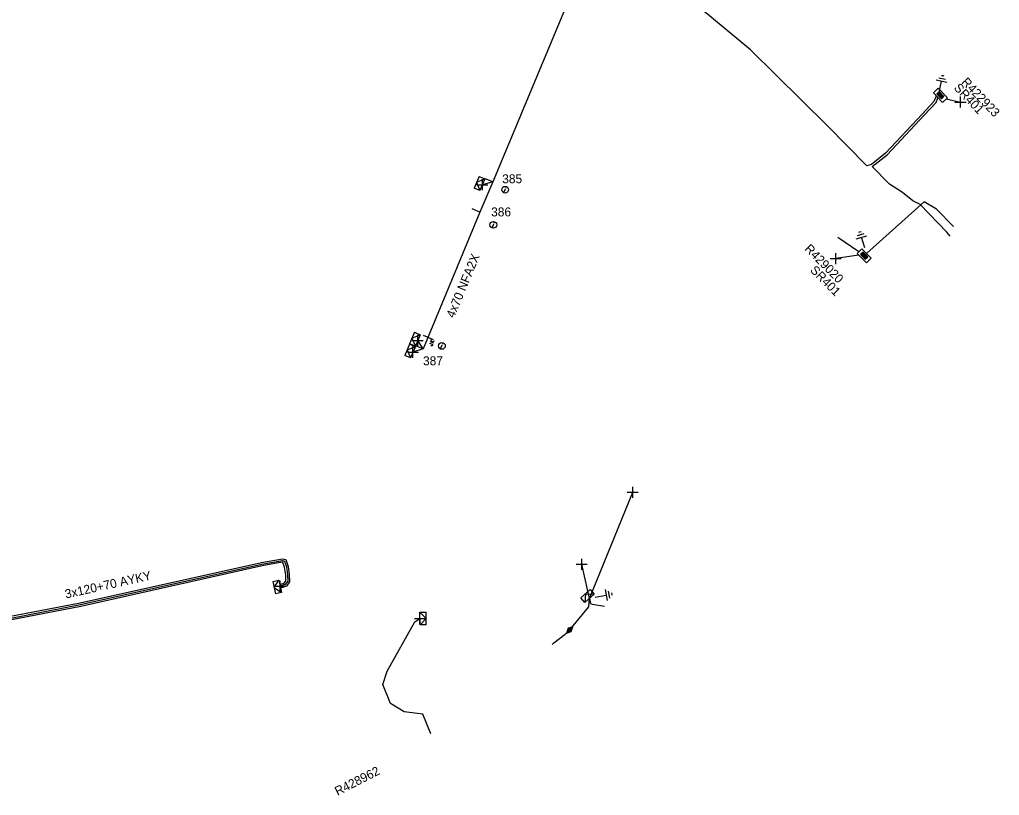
# Model space of a CAD drawing. Extents: x -540466 to -537383, y -1184038 to -1179972.
# Drawn here: x -538023.4 to -537913.7, y -1181000.4 to -1180913.5 of the extents above; entities that cross this region are included whole.
import ezdxf

# ---------------------------------------------------------------- set-up
doc = ezdxf.new("R2010")
doc.units = 0
for name, color, linetype in [('Vrstva 1', 7, 'Continuous'), ('Vrstva 10', 7, 'Continuous'), ('Vrstva 13', 7, 'Continuous'), ('Vrstva 14', 7, 'Continuous'), ('Vrstva 15', 7, 'Continuous'), ('Vrstva 18', 7, 'Continuous'), ('Vrstva 19', 7, 'Continuous'), ('Vrstva 2', 7, 'Continuous'), ('Vrstva 20', 7, 'Continuous'), ('Vrstva 28', 7, 'Continuous'), ('Vrstva 29', 7, 'Continuous'), ('Vrstva 30', 7, 'Continuous'), ('Vrstva 31', 7, 'Continuous'), ('Vrstva 34', 7, 'Continuous'), ('Vrstva 36', 7, 'Continuous'), ('Vrstva 4', 7, 'Continuous'), ('Vrstva 5', 7, 'Continuous'), ('Vrstva 50', 7, 'Continuous'), ('Vrstva 51', 7, 'Continuous'), ('Vrstva 52', 7, 'Continuous'), ('Vrstva 54', 7, 'Continuous'), ('Vrstva 59', 7, 'Continuous'), ('Vrstva 8', 7, 'Continuous'), ('Vrstva 9', 7, 'Continuous')]:
    doc.layers.add(name, color=color, linetype=linetype)

# ---------------------------------------------------------------- blocks, each defined once
blk = doc.blocks.new('NN840')
at = {"layer": 'Vrstva 15'}
for points in [[(0, 0.62), (0, -0.63)], [(-0.75, -0.71), (-0.75, -0.66)], [(-0.73, -0.76), (-0.75, -0.71)], [(-0.66, -0.8), (-0.73, -0.76)], [(-0.63, -0.8), (-0.66, -0.8)], [(-0.56, -0.76), (-0.63, -0.8)], [(-0.54, -0.71), (-0.56, -0.76)], [(-0.54, -0.38), (-0.54, -0.71)], [(-0.33, -0.38), (-0.33, -0.8)], [(-0.33, -0.64), (-0.13, -0.38)], [(-0.26, -0.56), (-0.09, -0.8)]]:
    blk.add_lwpolyline(points, dxfattribs=at)
blk = doc.blocks.new('NN770')
at = {"layer": 'Vrstva 10'}
for p, q in [((0, 0.19), (0, 0.26)), ((0, -0.28), (0, 0.11))]:
    blk.add_line(p, q, dxfattribs=at)
blk.add_circle((0, -0.01), 0.375, dxfattribs=at)
blk = doc.blocks.new('NN870')
at = {"layer": 'Vrstva 4'}
for points in [[(0, -0.25), (0.5, 0), (0, 0.25), (-0.5, 0), (0, -0.25)], [(0.37, 0), (0, 0.19), (-0.36, 0), (0, -0.19), (0.37, 0)], [(0.24, 0), (0, 0.12), (-0.25, 0), (0, -0.12), (0.24, 0)], [(0.12, 0), (0, 0.06), (-0.13, 0), (0, -0.06), (0.12, 0)]]:
    blk.add_lwpolyline(points, dxfattribs=at)
blk = doc.blocks.new('NN800')
at = {"layer": 'Vrstva 1'}
for points in [[(-0.44, 0.44), (0.44, -0.44)], [(-0.44, -0.44), (0.44, 0.44)]]:
    blk.add_lwpolyline(points, dxfattribs=at)
blk = doc.blocks.new('NN620')
at = {"layer": 'Vrstva 8'}
for points in [[(0.75, 0), (-0.75, 0)], [(-0.75, 0), (-0.75, -0.75)], [(0.75, -0.75), (0.75, 0)], [(-0.75, -0.75), (0.75, -0.75)], [(0.37, -0.18), (-0.38, -0.18)], [(-0.38, -0.18), (-0.38, -0.56)], [(-0.38, -0.56), (0.37, -0.56)], [(0.32, -0.23), (-0.33, -0.23)], [(-0.33, -0.23), (-0.33, -0.51)], [(-0.33, -0.51), (0.32, -0.51)], [(0.27, -0.27), (-0.28, -0.27)], [(-0.28, -0.27), (-0.28, -0.46)], [(-0.28, -0.46), (0.27, -0.46)], [(0.23, -0.32), (-0.23, -0.32)], [(-0.23, -0.32), (-0.23, -0.42)], [(-0.23, -0.42), (0.23, -0.42)], [(-0.19, -0.37), (0.19, -0.37)], [(0.23, -0.42), (0.23, -0.32)], [(0.27, -0.46), (0.27, -0.27)], [(0.32, -0.51), (0.32, -0.23)], [(0.37, -0.56), (0.37, -0.18)]]:
    blk.add_lwpolyline(points, dxfattribs=at)
blk = doc.blocks.new('NN630')
at = {"layer": 'Vrstva 9'}
for points in [[(0, -0.7), (-0.7, 0)], [(-0.7, -0.7), (-0.7, 0), (0.7, 0), (0.7, -0.7)], [(-0.7, -0.7), (0.7, -0.7)], [(0, -0.7), (0.7, 0)]]:
    blk.add_lwpolyline(points, dxfattribs=at)
blk = doc.blocks.new('NN810')
at = {"layer": 'Vrstva 14'}
for points in [[(0, -0.64), (0, -1.89)], [(0.63, -1.89), (-0.62, -1.89)], [(0.39, -2.2), (-0.4, -2.2)], [(0, -2.52), (-0.12, -2.52)], [(0.14, -2.52), (0, -2.52)]]:
    blk.add_lwpolyline(points, dxfattribs=at)
blk = doc.blocks.new('NN510')
at = {"layer": 'Vrstva 2'}
blk.add_lwpolyline([(0, 0), (0, 0.94)], dxfattribs=at)

msp = doc.modelspace()

# ---------------------------------------------------------------- linework, layer by layer
at = {"layer": 'Vrstva 20'}
msp.add_lwpolyline([(-538024.59, -1180980.38), (-538016.63, -1180978.83), (-537996.31, -1180974.31), (-537993.95, -1180973.9), (-537993.58, -1180974), (-537993.32, -1180974.75), (-537993.2, -1180975.69), (-537993.16, -1180976.48), (-537993.52, -1180976.98), (-537994.06, -1180977.14), (-537994.12, -1180976.75), (-537993.76, -1180976.63), (-537993.56, -1180976.36), (-537993.59, -1180975.73), (-537993.71, -1180974.85), (-537993.9, -1180974.32), (-537993.97, -1180974.3), (-537996.23, -1180974.71), (-538016.55, -1180979.23), (-538024.51, -1180980.78)], dxfattribs=at)
at = {"layer": 'Vrstva 5'}
for points in [[(-537920.72, -1180922.08), (-537921, -1180922.7), (-537922.25, -1180924.05), (-537926.4, -1180928.48), (-537927.97, -1180929.72), (-537928.51, -1180929.89), (-537932.95, -1180925.36), (-537941.54, -1180916.91), (-537948.5, -1180911.08), (-537955.38, -1180906.48), (-537957.79, -1180904.89), (-537958.59, -1180904.25), (-537956.41, -1180898.94), (-537955.84, -1180898.9)], [(-537919.17, -1180937.76), (-537919.53, -1180937.3), (-537922.53, -1180934.23), (-537923.36, -1180933.79), (-537924.49, -1180932.89), (-537925.95, -1180931.95), (-537927.9, -1180929.95), (-537926.22, -1180928.66), (-537922.07, -1180924.23), (-537920.75, -1180922.81), (-537920.54, -1180922.27)], [(-537918.81, -1180936.67), (-537920.71, -1180934.74), (-537922.07, -1180933.91), (-537928.51, -1180939.68)], [(-537961.78, -1180981.87), (-537959.63, -1180979.28), (-537959.55, -1180978.34)], [(-537959.55, -1180978.34), (-537959.44, -1180978.9), (-537959.27, -1180978.99), (-537957.9, -1180979.2)], [(-537963.75, -1180983.52), (-537963.54, -1180983.31), (-537962.28, -1180982.35), (-537961.78, -1180981.87)]]:
    msp.add_lwpolyline(points, dxfattribs=at)
at = {"layer": 'Vrstva 50'}
msp.add_lwpolyline([(-537954.21, -1180897.96), (-537961.26, -1180909.73), (-537970.4, -1180931.69), (-537971.83, -1180935.08), (-537978.18, -1180950.4)], dxfattribs=at)
at = {"layer": 'Vrstva 52'}
for points in [[(-538038.64, -1180989.07), (-538039.01, -1180989.18), (-538039.9, -1180987.66), (-538040.12, -1180986.67), (-538039.95, -1180985.79), (-538039.31, -1180984.57), (-538038.35, -1180983.69), (-538037.2, -1180983.2), (-538030.5, -1180981.83), (-538024.55, -1180980.58), (-538016.59, -1180979.03), (-537996.27, -1180974.51), (-537993.96, -1180974.1), (-537993.74, -1180974.16), (-537993.52, -1180974.8), (-537993.4, -1180975.71), (-537993.36, -1180976.42), (-537993.64, -1180976.8), (-537994.21, -1180976.98)], [(-537977.32, -1180993.52), (-537978.25, -1180991.3), (-537980.34, -1180991.06), (-537981.86, -1180990.11), (-537982.72, -1180988), (-537982.23, -1180986.5), (-537979.12, -1180980.96), (-537978.56, -1180980.6)]]:
    msp.add_lwpolyline(points, dxfattribs=at)
at = {"layer": 'Vrstva 59'}
for points in [[(-537919.62, -1180922.39), (-537918.01, -1180922.74)], [(-537929.4, -1180939.52), (-537931.75, -1180937.91)], [(-537929.4, -1180939.89), (-537931.99, -1180940.28)], [(-537959.55, -1180978.34), (-537954.72, -1180966.45)], [(-537959.55, -1180978.34), (-537960.44, -1180974.52)]]:
    msp.add_lwpolyline(points, dxfattribs=at)
at = {"layer": 'Vrstva 8'}
for points in [[(-537970.4, -1180931.69), (-537971.56, -1180932)], [(-537978.18, -1180950.4), (-537979.34, -1180950.76)], [(-537978.18, -1180950.4), (-537978.8, -1180949.45)]]:
    msp.add_lwpolyline(points, dxfattribs=at)

# ---------------------------------------------------------------- block references
at = {"layer": 'Vrstva 13'}
for p, rotation in [((-537970.4, -1180931.69), 67.35372217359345), ((-537971.83, -1180935.08), 67.48990278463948), ((-537978.18, -1180950.4), 67.48990278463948)]:
    msp.add_blockref('NN510', p, dxfattribs=dict(at, rotation=rotation))
at = {"layer": 'Vrstva 15'}
for p, rotation in [((-537920.53, -1180922.25), 167.77693617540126), ((-537928.53, -1180939.7), -163.03526380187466), ((-537959.55, -1180978.34), 101.11304164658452)]:
    msp.add_blockref('NN810', p, dxfattribs=dict(at, rotation=rotation))
at = {"layer": 'Vrstva 18', "rotation": 67.47577774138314}
msp.add_blockref('NN840', (-537977.64, -1180949.1), dxfattribs=at)
at = {"layer": 'Vrstva 19', "rotation": 43.830861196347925}
msp.add_blockref('NN870', (-537961.78, -1180981.87), dxfattribs=at)
at = {"layer": 'Vrstva 28'}
for p, rotation in [((-537920.53, -1180922.25), 133.52772788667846), ((-537928.53, -1180939.7), -45.388208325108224)]:
    msp.add_blockref('NN620', p, dxfattribs=dict(at, rotation=rotation))
at = {"layer": 'Vrstva 31'}
for p, rotation in [((-537971.56, -1180932), -112.64627771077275), ((-537978.8, -1180949.45), -112.51009721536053), ((-537979.34, -1180950.76), -112.60085835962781), ((-537994.21, -1180976.98), -77.94571389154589), ((-537959.55, -1180978.34), -137.8670222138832), ((-537978.56, -1180980.6), 91.1107749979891)]:
    msp.add_blockref('NN630', p, dxfattribs=dict(at, rotation=rotation))
at = {"layer": 'Vrstva 34'}
for p, rotation in [((-537918.01, -1180922.74), 45), ((-537971.56, -1180932), 45), ((-537931.99, -1180940.28), 45), ((-537978.8, -1180949.45), 45), ((-537979.34, -1180950.76), 45), ((-537954.72, -1180966.45), 45), ((-537960.44, -1180974.52), 44.99999995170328), ((-537994.21, -1180976.98), 45), ((-537978.56, -1180980.6), 45)]:
    msp.add_blockref('NN800', p, dxfattribs=dict(at, rotation=rotation))
at = {"layer": 'Vrstva 36'}
for p, rotation in [((-537969.01, -1180932.55), -22.65278045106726), ((-537970.33, -1180936.49), -22.516433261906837), ((-537976.09, -1180950.05), -22.516433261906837)]:
    msp.add_blockref('NN770', p, dxfattribs=dict(at, rotation=rotation))

# ---------------------------------------------------------------- texts
at = {"layer": 'Vrstva 14'}
for s, p in [('385', (-537969.34, -1180931.84)), ('386', (-537970.58, -1180935.55)), ('387', (-537978.21, -1180952.23))]:
    msp.add_text(s, height=1, dxfattribs=at).set_placement(p)
at = {"layer": 'Vrstva 29'}
for s, rotation, p in [('R422923', 313.528, (-537917.97, -1180920.57)), ('R429020', 314.612, (-537935.54, -1180939.26)), ('R428962', 27.09, (-537987.78, -1181000.46))]:
    msp.add_text(s, height=1, rotation=rotation, dxfattribs=at).set_placement(p)
at = {"layer": 'Vrstva 30'}
for rotation, p in [(313.528, (-537918.82, -1180921.22)), (314.612, (-537934.92, -1180941.65))]:
    msp.add_text('SR401', height=1, rotation=rotation, dxfattribs=at).set_placement(p)
at = {"layer": 'Vrstva 51'}
msp.add_text('4x70 NFA2X', height=1, rotation=67.476, dxfattribs=at).set_placement((-537974.74, -1180947.01))
at = {"layer": 'Vrstva 54'}
msp.add_text('3x120+70 AYKY', height=1, rotation=12.541, dxfattribs=at).set_placement((-538018.2, -1180978.36))

doc.saveas('drawing.dxf')
